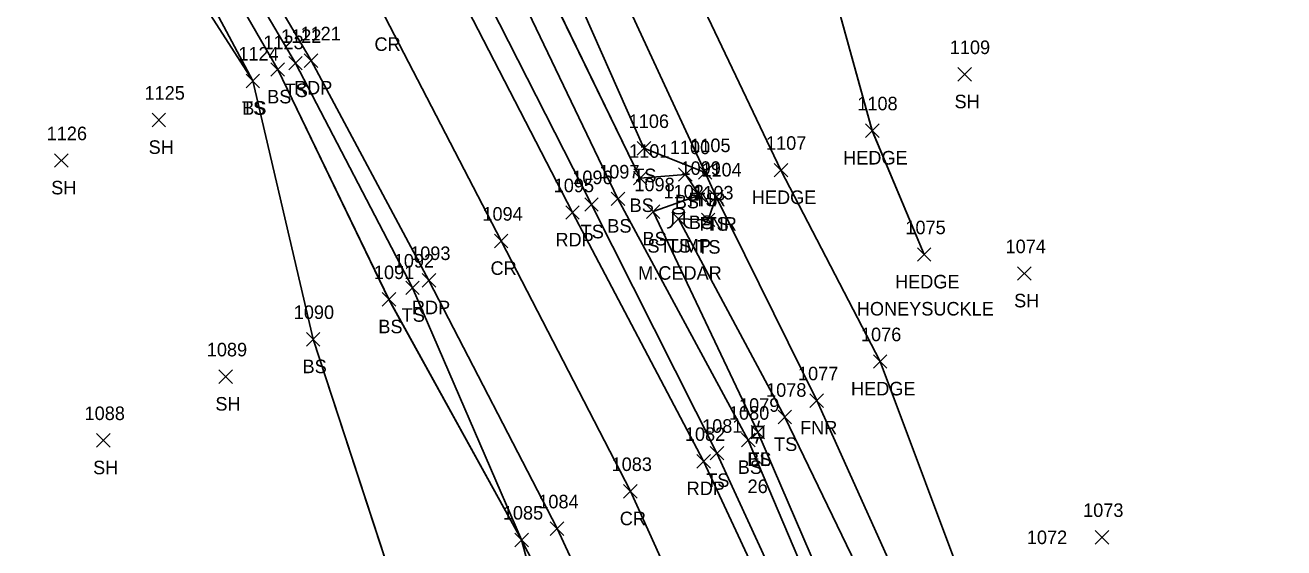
# Model space of a CAD drawing. Extents: x 1415642 to 1422021, y 544543 to 547232.
# Drawn here: x 1416447 to 1416632.7, y 546334.5 to 546411.7 of the extents above; entities that cross this region are included whole.
import ezdxf

# ---------------------------------------------------------------- set-up
doc = ezdxf.new("R2010")
doc.units = 0
for name, color, linetype in [('L_A', 7, 'Continuous'), ('L_C', 7, 'Continuous'), ('L_I', 7, 'Continuous'), ('L_TIC', 7, 'Continuous'), ('LAHR', 7, 'Continuous'), ('LELB', 7, 'Continuous'), ('LFNC', 7, 'Continuous'), ('LTS', 7, 'Continuous'), ('P_A', 7, 'Continuous'), ('P_I', 7, 'Continuous'), ('P_TIC', 7, 'Continuous'), ('PET', 7, 'Continuous'), ('PRC', 7, 'Continuous'), ('U_A', 7, 'Continuous'), ('U_C', 7, 'Continuous'), ('U_I', 7, 'Continuous'), ('UEPT', 7, 'Continuous')]:
    doc.layers.add(name, color=color, linetype=linetype)

msp = doc.modelspace()

# ---------------------------------------------------------------- linework, layer by layer
at = {"layer": 'L_TIC'}
for points in [[(1416483.25, 546404.14), (1416485.25, 546406.14)], [(1416485.25, 546404.14), (1416483.25, 546406.14)], [(1416485.87, 546405.07), (1416487.87, 546407.07)], [(1416487.87, 546405.07), (1416485.87, 546407.07)], [(1416479.57, 546402.46), (1416481.57, 546404.46)], [(1416481.57, 546402.46), (1416479.57, 546404.46)], [(1416479.57, 546402.46), (1416481.57, 546404.46)], [(1416481.57, 546402.46), (1416479.57, 546404.46)], [(1416584.6, 546403.42), (1416586.6, 546405.42)], [(1416586.6, 546403.42), (1416584.6, 546405.42)], [(1416465.71, 546396.69), (1416467.71, 546398.69)], [(1416467.71, 546396.69), (1416465.71, 546398.69)], [(1416570.96, 546395.12), (1416572.96, 546397.12)], [(1416572.96, 546395.12), (1416570.96, 546397.12)], [(1416537.28, 546392.51), (1416539.28, 546394.51)], [(1416539.28, 546392.51), (1416537.28, 546394.51)], [(1416451.34, 546390.71), (1416453.34, 546392.71)], [(1416453.34, 546390.71), (1416451.34, 546392.71)], [(1416557.49, 546389.29), (1416559.49, 546391.29)], [(1416559.49, 546389.29), (1416557.49, 546391.29)], [(1416536.72, 546388.11), (1416538.72, 546390.11)], [(1416538.72, 546388.11), (1416536.72, 546390.11)], [(1416543.38, 546388.65), (1416545.38, 546390.65)], [(1416545.38, 546388.65), (1416543.38, 546390.65)], [(1416546.3, 546388.95), (1416548.3, 546390.95)], [(1416548.3, 546388.95), (1416546.3, 546390.95)], [(1416546.3, 546388.95), (1416548.3, 546390.95)], [(1416548.3, 546388.95), (1416546.3, 546390.95)], [(1416545.45, 546385.59), (1416547.45, 546387.59)], [(1416547.45, 546385.59), (1416545.45, 546387.59)], [(1416529.53, 546384.22), (1416531.53, 546386.22)], [(1416531.53, 546384.22), (1416529.53, 546386.22)], [(1416533.43, 546385.06), (1416535.43, 546387.06)], [(1416535.43, 546385.06), (1416533.43, 546387.06)], [(1416547.95, 546385.35), (1416549.95, 546387.35)], [(1416549.95, 546385.35), (1416547.95, 546387.35)], [(1416547.95, 546385.35), (1416549.95, 546387.35)], [(1416549.95, 546385.35), (1416547.95, 546387.35)], [(1416538.63, 546383.17), (1416540.63, 546385.17)], [(1416540.63, 546383.17), (1416538.63, 546385.17)], [(1416542.37, 546382.11), (1416544.37, 546384.11)], [(1416544.37, 546382.11), (1416542.37, 546384.11)], [(1416546.74, 546381.96), (1416548.74, 546383.96)], [(1416548.74, 546381.96), (1416546.74, 546383.96)], [(1416578.62, 546376.83), (1416580.62, 546378.83)], [(1416580.62, 546376.83), (1416578.62, 546378.83)], [(1416593.39, 546374.03), (1416595.39, 546376.03)], [(1416595.39, 546374.03), (1416593.39, 546376.03)], [(1416503.13, 546371.91), (1416505.13, 546373.91)], [(1416505.13, 546371.91), (1416503.13, 546373.91)], [(1416499.65, 546370.21), (1416501.65, 546372.21)], [(1416501.65, 546370.21), (1416499.65, 546372.21)], [(1416488.47, 546364.32), (1416490.47, 546366.32)], [(1416490.47, 546364.32), (1416488.47, 546366.32)], [(1416572.12, 546361.04), (1416574.12, 546363.04)], [(1416574.12, 546361.04), (1416572.12, 546363.04)], [(1416475.56, 546358.8), (1416477.56, 546360.8)], [(1416477.56, 546358.8), (1416475.56, 546360.8)], [(1416562.77, 546355.27), (1416564.77, 546357.27)], [(1416564.77, 546355.27), (1416562.77, 546357.27)], [(1416558.06, 546352.84), (1416560.06, 546354.84)], [(1416560.06, 546352.84), (1416558.06, 546354.84)], [(1416554.08, 546350.62), (1416556.08, 546352.62)], [(1416556.08, 546350.62), (1416554.08, 546352.62)], [(1416457.52, 546349.4), (1416459.52, 546351.4)], [(1416459.52, 546349.4), (1416457.52, 546351.4)], [(1416552.66, 546349.45), (1416554.66, 546351.45)], [(1416554.66, 546349.45), (1416552.66, 546351.45)], [(1416548.05, 546347.52), (1416550.05, 546349.52)], [(1416550.05, 546347.52), (1416548.05, 546349.52)], [(1416519.22, 546334.71), (1416521.22, 546336.71)], [(1416521.22, 546334.71), (1416519.22, 546336.71)], [(1416519.22, 546334.71), (1416521.22, 546336.71)], [(1416521.22, 546334.71), (1416519.22, 546336.71)], [(1416604.84, 546335.1), (1416606.84, 546337.1)], [(1416606.84, 546335.1), (1416604.84, 546337.1)]]:
    msp.add_lwpolyline(points, dxfattribs=at)
at = {"layer": 'LAHR'}
for points in [[(1416601.24, 546292.69), (1416586.35, 546326.71), (1416573.12, 546362.04), (1416558.49, 546390.29), (1416537.49, 546434.36), (1416523.93, 546467.1), (1416523.32, 546471.61)], [(1416601.24, 546292.69), (1416586.35, 546326.71), (1416573.12, 546362.03), (1416558.49, 546390.29), (1416537.49, 546434.36), (1416523.93, 546467.1), (1416523.32, 546471.61)], [(1416579.62, 546377.83), (1416571.96, 546396.11), (1416561.88, 546432.63), (1416555.38, 546459.56)], [(1416579.62, 546377.83), (1416571.96, 546396.12), (1416561.88, 546432.63), (1416555.38, 546459.55)]]:
    msp.add_lwpolyline(points, dxfattribs=at)
at = {"layer": 'LELB'}
for points in [[(1416578, 546177.77), (1416578.55, 546199.27), (1416573.9, 546214.14), (1416552.43, 546269), (1416536.22, 546304.5), (1416520.22, 546335.71), (1416500.65, 546371.21), (1416484.25, 546405.14), (1416455.06, 546455.78), (1416435.93, 546486.65), (1416412.14, 546519.01), (1416383.64, 546557.13), (1416352.74, 546592.54), (1416331.82, 546618.14), (1416293.94, 546655.61), (1416274.22, 546680.91), (1416245.72, 546708.98), (1416224.27, 546729.93), (1416198.14, 546753.3), (1416170.94, 546765.48), (1416158.5, 546767.31), (1416141.08, 546772.75), (1416136.01, 546776.95), (1416129, 546780.64)], [(1416578, 546177.77), (1416578.55, 546199.27), (1416573.9, 546214.14), (1416552.42, 546269.01), (1416536.22, 546304.5), (1416520.22, 546335.71), (1416500.65, 546371.22), (1416484.25, 546405.15), (1416455.06, 546455.79), (1416435.93, 546486.65), (1416412.14, 546519.01), (1416383.65, 546557.13), (1416352.74, 546592.54), (1416331.82, 546618.14), (1416293.94, 546655.62), (1416274.22, 546680.91), (1416245.72, 546708.98), (1416224.27, 546729.93), (1416198.14, 546753.3), (1416170.94, 546765.48), (1416158.51, 546767.31), (1416141.09, 546772.75), (1416136.01, 546776.96), (1416129.01, 546780.64)], [(1416503.76, 546247.98), (1416498.74, 546274.69), (1416501.23, 546308.66), (1416502.98, 546324.04), (1416489.47, 546365.32), (1416480.57, 546403.46), (1416453.11, 546455.02), (1416433.2, 546484.78), (1416409.26, 546516.78), (1416378.25, 546552.92), (1416343.61, 546583.91), (1416327.57, 546614.09), (1416289.4, 546651.59), (1416267.58, 546675.69), (1416237.14, 546697.31), (1416220.66, 546725.9), (1416195.41, 546750.9), (1416170.78, 546763.33), (1416158.82, 546764.49), (1416140.16, 546770.72), (1416135.4, 546775.05), (1416128.27, 546778.63)], [(1416503.76, 546247.98), (1416498.74, 546274.69), (1416501.24, 546308.65), (1416502.98, 546324.03), (1416489.47, 546365.32), (1416480.57, 546403.46), (1416453.11, 546455.02), (1416433.2, 546484.78), (1416409.26, 546516.79), (1416378.25, 546552.92), (1416343.61, 546583.91), (1416327.58, 546614.09), (1416289.4, 546651.59), (1416267.58, 546675.69), (1416237.14, 546697.31), (1416220.66, 546725.9), (1416195.42, 546750.9), (1416170.78, 546763.33), (1416158.81, 546764.5), (1416140.16, 546770.72), (1416135.4, 546775.05), (1416128.28, 546778.62)], [(1416480.57, 546403.46), (1416449.3, 546452.17), (1416431.01, 546483.64), (1416405.55, 546512.84), (1416372.51, 546548.53), (1416341.49, 546581.99), (1416324.84, 546612.16), (1416286, 546648.13), (1416263.12, 546671.71)], [(1416480.57, 546403.46), (1416449.3, 546452.17), (1416431.01, 546483.64), (1416405.56, 546512.84), (1416372.51, 546548.53), (1416341.49, 546581.99), (1416324.84, 546612.16), (1416286, 546648.13), (1416263.12, 546671.71)], [(1416587.9, 546190.79), (1416583.62, 546199.97), (1416577.46, 546215.02), (1416552.43, 546269), (1416533.39, 546301.47), (1416525.26, 546316.84), (1416520.22, 546335.71), (1416504.13, 546372.91), (1416486.87, 546406.07), (1416456.87, 546456.96), (1416435.93, 546486.65), (1416413.88, 546519.84), (1416385.73, 546558.12)], [(1416587.91, 546190.79), (1416583.61, 546199.97), (1416577.46, 546215.02), (1416552.42, 546269.01), (1416533.39, 546301.47), (1416525.26, 546316.84), (1416520.22, 546335.71), (1416504.13, 546372.91), (1416486.87, 546406.07), (1416456.87, 546456.96), (1416435.93, 546486.65), (1416413.88, 546519.84), (1416385.73, 546558.12)], [(1416547.3, 546389.95), (1416538.28, 546393.51), (1416524.42, 546424.83), (1416510.94, 546457.47), (1416508.34, 546472.94), (1416503.17, 546479.89), (1416498.12, 546480.46), (1416491.26, 546472.3), (1416490.18, 546459.78)], [(1416547.3, 546389.95), (1416538.28, 546393.51), (1416524.42, 546424.83), (1416510.95, 546457.47), (1416508.35, 546472.93), (1416503.17, 546479.89), (1416498.12, 546480.46), (1416491.25, 546472.3), (1416490.18, 546459.78)], [(1416624.83, 546188.33), (1416609.68, 546228.85), (1416587.46, 546280.33), (1416569.58, 546317.95), (1416555.08, 546351.62), (1416539.63, 546384.17), (1416546.45, 546386.59), (1416544.38, 546389.65), (1416537.72, 546389.11), (1416521.41, 546422.69), (1416507.02, 546457.32), (1416500.86, 546474.51), (1416499.33, 546475.96), (1416498.77, 546475.76), (1416499.17, 546473.82)], [(1416624.83, 546188.34), (1416609.68, 546228.85), (1416587.45, 546280.34), (1416569.58, 546317.95), (1416555.08, 546351.63), (1416539.63, 546384.17), (1416546.45, 546386.59), (1416544.38, 546389.64), (1416537.72, 546389.12), (1416521.42, 546422.68), (1416507.02, 546457.32), (1416500.87, 546474.51), (1416499.33, 546475.96), (1416498.77, 546475.76), (1416499.17, 546473.83)], [(1416624.13, 546188.48), (1416606.9, 546227.58), (1416585.22, 546279.32), (1416567.76, 546317.19), (1416553.66, 546350.45), (1416534.43, 546386.06), (1416517.2, 546422.02), (1416505.52, 546457.03), (1416499.17, 546473.83)], [(1416624.13, 546188.48), (1416606.9, 546227.58), (1416585.22, 546279.32), (1416567.76, 546317.19), (1416553.66, 546350.45), (1416534.43, 546386.06), (1416517.2, 546422.01), (1416505.52, 546457.03), (1416499.17, 546473.82)], [(1416620.93, 546187.09), (1416604.47, 546226.81), (1416580.95, 546278.02), (1416564.18, 546315.62), (1416549.05, 546348.52), (1416530.53, 546385.22), (1416512.89, 546419.96), (1416490.18, 546459.78)], [(1416620.93, 546187.09), (1416604.48, 546226.8), (1416580.95, 546278.02), (1416564.18, 546315.62), (1416549.05, 546348.51), (1416530.53, 546385.22), (1416512.89, 546419.96), (1416490.18, 546459.78)], [(1416632.67, 546189.86), (1416612.14, 546229.74), (1416591.55, 546282.91), (1416575.19, 546320.43), (1416559.06, 546353.84), (1416543.37, 546383.11), (1416547.74, 546382.96), (1416548.95, 546386.35)], [(1416632.67, 546189.86), (1416612.15, 546229.74), (1416591.55, 546282.91), (1416575.19, 546320.43), (1416559.06, 546353.84), (1416543.37, 546383.11), (1416547.74, 546382.97), (1416548.95, 546386.35)]]:
    msp.add_lwpolyline(points, dxfattribs=at)
at = {"layer": 'LFNC'}
for points in [[(1416616.17, 546291.53), (1416602.64, 546290.41), (1416594.37, 546289.3), (1416578.97, 546322.54), (1416563.77, 546356.27), (1416548.95, 546386.35), (1416547.3, 546389.95), (1416530.29, 546426.68), (1416513.55, 546462.2), (1416508.34, 546472.94), (1416504.48, 546483), (1416512.48, 546489.98)], [(1416616.17, 546291.53), (1416602.64, 546290.41), (1416594.37, 546289.3), (1416578.97, 546322.54), (1416563.77, 546356.27), (1416548.95, 546386.35), (1416547.3, 546389.95), (1416530.29, 546426.68), (1416513.55, 546462.2), (1416508.35, 546472.93), (1416504.48, 546483), (1416512.48, 546489.98)]]:
    msp.add_lwpolyline(points, dxfattribs=at)
at = {"layer": 'LTS'}
for p, q in [((1416542.54, 546384.25), (1416542.54, 546382.58)), ((1416544.21, 546384.08), (1416544.21, 546384.25)), ((1416544.21, 546384.25), (1416544.21, 546382.58)), ((1416543.37, 546383.11), (1416543.37, 546383.11)), ((1416543.37, 546383.11), (1416543.37, 546383.11)), ((1416543.37, 546383.08), (1416543.37, 546383.08))]:
    msp.add_line(p, q, dxfattribs=at)
msp.add_circle((1416543.37, 546383.11), 0.0833, dxfattribs=at)
for centre, start, end in [((1416541.71, 546382.58), 270, 360), ((1416545.04, 546382.58), 180, 270)]:
    msp.add_arc(centre, 0.833, start, end, dxfattribs=at)
msp.add_ellipse((1416543.37, 546384.25), major_axis=(-0.833, 0), ratio=0.5, dxfattribs=at)
at = {"layer": 'P_TIC'}
for points in [[(1416488.16, 546405.45), (1416490.16, 546407.45)], [(1416490.16, 546405.45), (1416488.16, 546407.45)], [(1416526.73, 546383.03), (1416528.73, 546385.03)], [(1416528.73, 546383.03), (1416526.73, 546385.03)], [(1416516.21, 546378.83), (1416518.21, 546380.83)], [(1416518.21, 546378.83), (1416516.21, 546380.83)], [(1416505.55, 546373.02), (1416507.55, 546375.02)], [(1416507.55, 546373.02), (1416505.55, 546375.02)], [(1416546.08, 546346.32), (1416548.08, 546348.32)], [(1416548.08, 546346.32), (1416546.08, 546348.32)], [(1416535.28, 546341.88), (1416537.28, 546343.88)], [(1416537.28, 546341.88), (1416535.28, 546343.88)], [(1416524.46, 546336.37), (1416526.46, 546338.37)], [(1416526.46, 546336.37), (1416524.46, 546338.37)]]:
    msp.add_lwpolyline(points, dxfattribs=at)
at = {"layer": 'PET'}
for points in [[(1416619.56, 546186.67), (1416601.63, 546226.16), (1416579.47, 546277.45), (1416562.03, 546315.23), (1416547.08, 546347.32), (1416527.73, 546384.04), (1416509.97, 546418.47), (1416487.43, 546457.37), (1416462.82, 546495.68), (1416435.56, 546537.44), (1416408.53, 546574.62)], [(1416619.56, 546186.67), (1416601.62, 546226.16), (1416579.47, 546277.45), (1416562.03, 546315.23), (1416547.08, 546347.32), (1416527.73, 546384.03), (1416509.97, 546418.46), (1416487.43, 546457.37), (1416462.82, 546495.68), (1416435.56, 546537.44), (1416408.53, 546574.61)], [(1416599.36, 546175.05), (1416589.42, 546196.6), (1416580.61, 546216.08), (1416556.35, 546269.48), (1416540.49, 546305), (1416525.46, 546337.37), (1416506.55, 546374.02), (1416489.16, 546406.45), (1416459.13, 546457.37), (1416438.7, 546488.16), (1416417.68, 546520.98), (1416388.9, 546560.28)], [(1416599.36, 546175.05), (1416589.42, 546196.6), (1416580.62, 546216.08), (1416556.34, 546269.48), (1416540.49, 546305), (1416525.46, 546337.38), (1416506.55, 546374.02), (1416489.16, 546406.45), (1416459.13, 546457.38), (1416438.7, 546488.17), (1416417.68, 546520.98), (1416388.9, 546560.28)]]:
    msp.add_lwpolyline(points, dxfattribs=at)
at = {"layer": 'PRC'}
for points in [[(1416610.25, 546183.67), (1416586.12, 546227.19), (1416567.64, 546274.51), (1416551.19, 546309.95), (1416536.28, 546342.88), (1416517.21, 546379.83), (1416500.09, 546412.89), (1416469.99, 546464.05), (1416448.59, 546494.95), (1416427.64, 546528.31), (1416425.29, 546532.23), (1416399.16, 546568.17)], [(1416610.26, 546183.67), (1416586.11, 546227.19), (1416567.64, 546274.51), (1416551.18, 546309.96), (1416536.27, 546342.88), (1416517.21, 546379.83), (1416500.09, 546412.89), (1416469.99, 546464.05), (1416448.59, 546494.95), (1416427.64, 546528.31), (1416425.29, 546532.24), (1416399.16, 546568.17)]]:
    msp.add_lwpolyline(points, dxfattribs=at)
at = {"layer": 'UEPT'}
for p, q in [((1416554.25, 546350.79), (1416554.25, 546352.46)), ((1416554.25, 546352.46), (1416555.91, 546352.46)), ((1416555.25, 546353.29), (1416555.08, 546352.46)), ((1416555.91, 546352.46), (1416555.91, 546350.79)), ((1416555.91, 546350.79), (1416554.25, 546350.79)), ((1416554.83, 546349.96), (1416555.08, 546350.79)), ((1416555.08, 546351.62), (1416555.08, 546351.62))]:
    msp.add_line(p, q, dxfattribs=at)

# ---------------------------------------------------------------- texts
at = {"layer": 'L_A'}
for s, p in [('TS', (1416485.28, 546401.07)), ('TS', (1416478.98, 546398.46)), ('BS', (1416479.01, 546398.46)), ('BS', (1416482.69, 546400.14)), ('SH', (1416584.09, 546399.42)), ('SH', (1416465.2, 546392.69)), ('HEDGE', (1416567.66, 546391.12)), ('TS', (1416536.69, 546388.51)), ('SH', (1416450.83, 546386.71)), ('BS', (1416536.16, 546384.11)), ('BS', (1416542.82, 546384.65)), ('FNR', (1416544.84, 546384.95)), ('TS', (1416545.71, 546384.95)), ('HEDGE', (1416554.19, 546385.29)), ('TS', (1416528.94, 546380.22)), ('BS', (1416532.87, 546381.06)), ('BS', (1416544.89, 546381.59)), ('FNR', (1416546.48, 546381.35)), ('TS', (1416547.36, 546381.35)), ('BS', (1416538.07, 546379.17)), ('STUMP', (1416538.79, 546378.11)), ('TS', (1416541.78, 546378.11)), ('TS', (1416546.15, 546377.96)), ('HEDGE', (1416575.32, 546372.83)), ('SH', (1416592.88, 546370.03)), ('TS', (1416502.54, 546367.91)), ('BS', (1416499.09, 546366.21)), ('BS', (1416487.91, 546360.32)), ('HEDGE', (1416568.82, 546357.04)), ('SH', (1416475.05, 546354.8)), ('FNR', (1416561.31, 546351.27)), ('TS', (1416557.47, 546348.84)), ('BS', (1416553.52, 546346.62)), ('SH', (1416457.01, 546345.4)), ('BS', (1416552.11, 546345.45)), ('TS', (1416547.46, 546343.52))]:
    msp.add_text(s, height=2, dxfattribs=at).set_placement(p)
at = {"layer": 'L_C'}
for s, p in [('M.CEDAR', (1416537.42, 546374.11)), ('HONEYSUCKLE', (1416569.68, 546368.83))]:
    msp.add_text(s, height=2, dxfattribs=at).set_placement(p)
at = {"layer": 'L_I'}
for s, p in [('1123', (1416482.13, 546408.14)), ('1122', (1416484.74, 546409.07)), ('1124', (1416478.44, 546406.46)), ('1124', (1416478.44, 546406.46)), ('1109', (1416583.39, 546407.42)), ('1125', (1416464.59, 546400.69)), ('1108', (1416569.75, 546399.12)), ('1106', (1416536.02, 546396.51)), ('1126', (1416450.16, 546394.71)), ('1105', (1416545.1, 546392.95)), ('1105', (1416545.1, 546392.95)), ('1107', (1416556.28, 546393.29)), ('1101', (1416536.08, 546392.11)), ('1100', (1416542.09, 546392.65)), ('1097', (1416531.66, 546389.06)), ('1099', (1416543.67, 546389.59)), ('1104', (1416546.74, 546389.35)), ('1104', (1416546.74, 546389.35)), ('1096', (1416527.7, 546388.22)), ('1098', (1416536.86, 546387.17)), ('1102', (1416541.16, 546386.11)), ('1102', (1416541.16, 546386.11)), ('1103', (1416545.53, 546385.96)), ('1075', (1416576.84, 546380.83)), ('1074', (1416591.62, 546378.03)), ('1091', (1416498.44, 546374.21)), ('1092', (1416501.36, 546375.91)), ('1090', (1416486.61, 546368.32)), ('1076', (1416570.29, 546365.04)), ('1089', (1416473.78, 546362.8)), ('1077', (1416561, 546359.27)), ('1078', (1416556.29, 546356.84)), ('1079', (1416552.3, 546354.62)), ('1088', (1416455.75, 546353.4)), ('1080', (1416550.81, 546353.45)), ('1081', (1416546.85, 546351.52)), ('1073', (1416603.06, 546339.1)), ('1085', (1416517.45, 546338.71)), ('1085', (1416517.45, 546338.71)), ('1072', (1416594.76, 546335.09))]:
    msp.add_text(s, height=2, dxfattribs=at).set_placement(p)
at = {"layer": 'P_A'}
for s, p in [('CR', (1416498.52, 546407.89)), ('RDP', (1416486.65, 546401.45)), ('RDP', (1416525.22, 546379.03)), ('CR', (1416515.64, 546374.83)), ('RDP', (1416504.04, 546369.02)), ('RDP', (1416544.57, 546342.32)), ('CR', (1416534.71, 546337.88))]:
    msp.add_text(s, height=2, dxfattribs=at).set_placement(p)
at = {"layer": 'P_I'}
for s, p in [('1121', (1416487.6, 546409.45)), ('1095', (1416524.96, 546387.03)), ('1094', (1416514.44, 546382.83)), ('1093', (1416503.78, 546377.02)), ('1082', (1416544.31, 546350.32)), ('1083', (1416533.5, 546345.88)), ('1084', (1416522.69, 546340.37))]:
    msp.add_text(s, height=2, dxfattribs=at).set_placement(p)
at = {"layer": 'U_A'}
msp.add_text('EL', height=2, dxfattribs=at).set_placement((1416553.61, 546346.62))
at = {"layer": 'U_C'}
msp.add_text('26', height=2, dxfattribs=at).set_placement((1416553.56, 546342.62))
at = {"layer": 'U_I'}
msp.add_text('1079', height=2, dxfattribs=at).set_placement((1416552.3, 546354.62))

doc.saveas('drawing.dxf')
